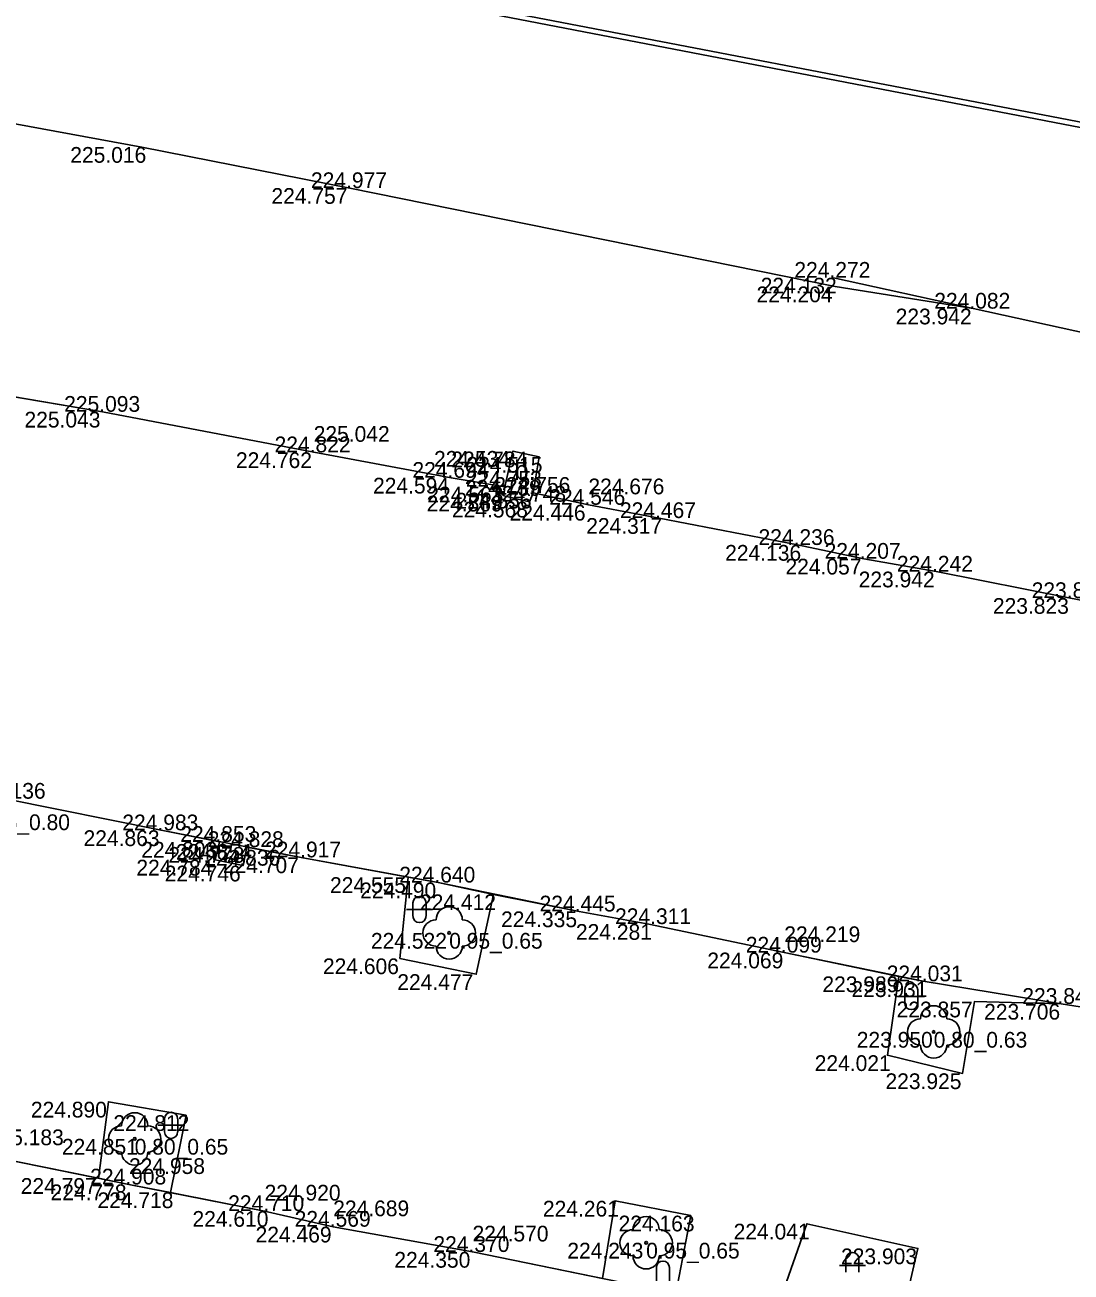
# Model space of a CAD drawing. Extents: x -599516 to -599132, y -1163668 to -1163119.
# Drawn here: x -599349.76 to -599329.8, y -1163179.4 to -1163155.61 of the extents above; entities that cross this region are included whole.
import ezdxf

# ---------------------------------------------------------------- set-up
doc = ezdxf.new("R2010")
doc.units = 0
for name, color, linetype in [('_ZEMERENI OBLAST', 7, 'Continuous'), ('Bod-oznac1', 7, 'Continuous'), ('Bod-oznac2', 7, 'Continuous'), ('Bod-oznac3', 7, 'Continuous'), ('Bod-vyska1', 7, 'Continuous'), ('Bod-vyska2', 7, 'Continuous'), ('Bod-vyska3', 7, 'Continuous'), ('Z_cela-hrobu-dolni-linie', 7, 'Continuous'), ('Z_cela-hrobu-horni-linie', 7, 'Continuous'), ('Z_komunikace', 7, 'Continuous'), ('Z_kultury-znacky', 7, 'Continuous'), ('Z_obvod-kmene-spodek-ve-vysce1_2m', 7, 'Continuous'), ('Z_popis-budov-povrchu', 7, 'Continuous'), ('Z_stromy-kere', 7, 'Continuous'), ('Z_zdi-ohradni', 7, 'Continuous'), ('Z_zpevnene-plochy', 7, 'Continuous')]:
    doc.layers.add(name, color=color, linetype=linetype)

msp = doc.modelspace()

# ---------------------------------------------------------------- linework, layer by layer
at = {"layer": '_ZEMERENI OBLAST'}
msp.add_lwpolyline([(-599246.21, -1163173.61), (-599310.76, -1163161.2), (-599382.471, -1163147.382), (-599418.511, -1163140.298), (-599415.805, -1163126.425), (-599441.73, -1163121.594), (-599445.004, -1163135.25), (-599483.712, -1163127.751), (-599506.25, -1163123.345), (-599510.771, -1163146.476), (-599502.636, -1163301.975), (-599510.038, -1163302.355), (-599510.12, -1163309.17), (-599515.16, -1163309.664), (-599511.204, -1163380.278), (-599506.35, -1163380.56), (-599506.01, -1163391.1), (-599497.946, -1163390.674), (-599491.96, -1163502.01)], dxfattribs=at)
at = {"layer": 'Bod-oznac1'}
for p, q in [((-599347.526, -1163157.941), (-599347.526, -1163157.941)), ((-599343.555, -1163158.724), (-599343.555, -1163158.724)), ((-599334.328, -1163160.434), (-599334.328, -1163160.434)), ((-599334.295, -1163160.601), (-599334.295, -1163160.601)), ((-599331.661, -1163161.023), (-599331.661, -1163161.023)), ((-599348.273, -1163162.99), (-599348.273, -1163162.99)), ((-599344.246, -1163163.763), (-599344.246, -1163163.763)), ((-599340.446, -1163163.738), (-599340.446, -1163163.738)), ((-599339.942, -1163163.851), (-599339.942, -1163163.851)), ((-599341.621, -1163164.249), (-599341.621, -1163164.249)), ((-599340.597, -1163164.419), (-599340.597, -1163164.419)), ((-599340.621, -1163164.591), (-599340.621, -1163164.591)), ((-599340.128, -1163164.705), (-599340.128, -1163164.705)), ((-599340.058, -1163164.536), (-599340.058, -1163164.536)), ((-599339.005, -1163164.764), (-599339.005, -1163164.764)), ((-599337.656, -1163165.017), (-599337.656, -1163165.017)), ((-599335.018, -1163165.53), (-599335.018, -1163165.53)), ((-599333.752, -1163165.793), (-599333.752, -1163165.793)), ((-599332.367, -1163166.038), (-599332.367, -1163166.038)), ((-599329.806, -1163166.543), (-599329.806, -1163166.543)), ((-599347.156, -1163170.972), (-599347.156, -1163170.972)), ((-599346.045, -1163171.192), (-599346.045, -1163171.192)), ((-599345.521, -1163171.291), (-599345.521, -1163171.291)), ((-599346.123, -1163171.534), (-599346.123, -1163171.534)), ((-599345.593, -1163171.646), (-599345.593, -1163171.646)), ((-599344.484, -1163171.488), (-599344.484, -1163171.488)), ((-599342.442, -1163171.866), (-599342.442, -1163171.866)), ((-599341.868, -1163171.968), (-599341.868, -1163171.968)), ((-599340.818, -1163172.194), (-599340.818, -1163172.194)), ((-599339.178, -1163172.519), (-599339.178, -1163172.519)), ((-599337.854, -1163172.76), (-599337.854, -1163172.76)), ((-599341.661, -1163172.929), (-599341.661, -1163172.929)), ((-599335.268, -1163173.304), (-599335.268, -1163173.304)), ((-599342.602, -1163173.415), (-599342.602, -1163173.415)), ((-599341.143, -1163173.716), (-599341.143, -1163173.716)), ((-599333.081, -1163173.758), (-599333.081, -1163173.758)), ((-599332.62, -1163173.851), (-599332.62, -1163173.851)), ((-599331.641, -1163174.239), (-599331.641, -1163174.239)), ((-599329.985, -1163174.282), (-599329.985, -1163174.282)), ((-599332.417, -1163174.817), (-599332.417, -1163174.817)), ((-599333.3, -1163175.262), (-599333.3, -1163175.262)), ((-599331.867, -1163175.607), (-599331.867, -1163175.607)), ((-599348.162, -1163176.149), (-599348.162, -1163176.149)), ((-599346.679, -1163176.405), (-599346.679, -1163176.405)), ((-599347.661, -1163176.857), (-599347.661, -1163176.857)), ((-599348.35, -1163177.605), (-599348.35, -1163177.605)), ((-599347.77, -1163177.726), (-599347.77, -1163177.726)), ((-599346.981, -1163177.877), (-599346.981, -1163177.877)), ((-599338.495, -1163178.038), (-599338.495, -1163178.038)), ((-599345.183, -1163178.233), (-599345.183, -1163178.233)), ((-599337.051, -1163178.321), (-599337.051, -1163178.321)), ((-599343.874, -1163178.532), (-599343.874, -1163178.532)), ((-599334.836, -1163178.475), (-599334.836, -1163178.475)), ((-599341.216, -1163179.013), (-599341.216, -1163179.013)), ((-599337.903, -1163178.838), (-599337.903, -1163178.838)), ((-599332.717, -1163178.947), (-599332.717, -1163178.947))]:
    msp.add_line(p, q, dxfattribs=at)
at = {"layer": 'Bod-oznac2'}
for p, q in [((-599343.555, -1163158.724), (-599343.555, -1163158.724)), ((-599334.328, -1163160.434), (-599334.328, -1163160.434)), ((-599331.661, -1163161.023), (-599331.661, -1163161.023)), ((-599348.273, -1163162.99), (-599348.273, -1163162.99)), ((-599344.246, -1163163.763), (-599344.246, -1163163.763)), ((-599341.621, -1163164.249), (-599341.621, -1163164.249)), ((-599340.597, -1163164.419), (-599340.597, -1163164.419)), ((-599340.621, -1163164.591), (-599340.621, -1163164.591)), ((-599340.128, -1163164.705), (-599340.128, -1163164.705)), ((-599340.058, -1163164.536), (-599340.058, -1163164.536)), ((-599339.005, -1163164.764), (-599339.005, -1163164.764)), ((-599337.656, -1163165.017), (-599337.656, -1163165.017)), ((-599335.018, -1163165.53), (-599335.018, -1163165.53)), ((-599333.752, -1163165.793), (-599333.752, -1163165.793)), ((-599332.367, -1163166.038), (-599332.367, -1163166.038)), ((-599329.806, -1163166.543), (-599329.806, -1163166.543)), ((-599347.156, -1163170.972), (-599347.156, -1163170.972)), ((-599346.045, -1163171.192), (-599346.045, -1163171.192)), ((-599345.521, -1163171.291), (-599345.521, -1163171.291)), ((-599346.123, -1163171.534), (-599346.123, -1163171.534)), ((-599345.593, -1163171.646), (-599345.593, -1163171.646)), ((-599344.484, -1163171.488), (-599344.484, -1163171.488)), ((-599341.868, -1163171.968), (-599341.868, -1163171.968)), ((-599339.178, -1163172.519), (-599339.178, -1163172.519)), ((-599337.854, -1163172.76), (-599337.854, -1163172.76)), ((-599335.268, -1163173.304), (-599335.268, -1163173.304)), ((-599332.62, -1163173.851), (-599332.62, -1163173.851)), ((-599329.985, -1163174.282), (-599329.985, -1163174.282)), ((-599347.77, -1163177.726), (-599347.77, -1163177.726)), ((-599345.183, -1163178.233), (-599345.183, -1163178.233)), ((-599343.874, -1163178.532), (-599343.874, -1163178.532)), ((-599341.216, -1163179.013), (-599341.216, -1163179.013))]:
    msp.add_line(p, q, dxfattribs=at)
at = {"layer": 'Bod-oznac3'}
for p, q in [((-599344.246, -1163163.763), (-599344.246, -1163163.763)), ((-599341.621, -1163164.249), (-599341.621, -1163164.249)), ((-599339.005, -1163164.764), (-599339.005, -1163164.764)), ((-599329.806, -1163166.543), (-599329.806, -1163166.543)), ((-599335.268, -1163173.304), (-599335.268, -1163173.304)), ((-599347.77, -1163177.726), (-599347.77, -1163177.726)), ((-599345.183, -1163178.233), (-599345.183, -1163178.233)), ((-599343.874, -1163178.532), (-599343.874, -1163178.532)), ((-599341.216, -1163179.013), (-599341.216, -1163179.013))]:
    msp.add_line(p, q, dxfattribs=at)
at = {"layer": 'Z_cela-hrobu-dolni-linie'}
msp.add_line((-599331.661, -1163161.023), (-599334.328, -1163160.434), dxfattribs=at)
for points in [[(-599340.597, -1163164.419), (-599340.621, -1163164.591), (-599340.128, -1163164.705), (-599340.058, -1163164.536)], [(-599342.442, -1163171.866), (-599341.868, -1163171.968), (-599340.818, -1163172.194)], [(-599333.081, -1163173.758), (-599332.62, -1163173.851), (-599329.985, -1163174.282)], [(-599346.981, -1163177.877), (-599347.77, -1163177.726), (-599348.35, -1163177.605)]]:
    msp.add_lwpolyline(points, dxfattribs=at)
at = {"layer": 'Z_cela-hrobu-horni-linie'}
for p, q in [((-599343.555, -1163158.724), (-599347.526, -1163157.941)), ((-599334.328, -1163160.434), (-599331.661, -1163161.023)), ((-599348.273, -1163162.99), (-599350.949, -1163162.537)), ((-599337.656, -1163165.017), (-599335.018, -1163165.53)), ((-599347.156, -1163170.972), (-599344.484, -1163171.488)), ((-599344.484, -1163171.488), (-599341.868, -1163171.968)), ((-599341.868, -1163171.968), (-599339.178, -1163172.519)), ((-599339.178, -1163172.519), (-599337.854, -1163172.76)), ((-599332.62, -1163173.851), (-599329.985, -1163174.282))]:
    msp.add_line(p, q, dxfattribs=at)
for points in [[(-599337.656, -1163165.017), (-599339.005, -1163164.764), (-599339.005, -1163164.764), (-599340.058, -1163164.536), (-599340.128, -1163164.705), (-599340.621, -1163164.591), (-599340.597, -1163164.419), (-599341.621, -1163164.249), (-599341.621, -1163164.249), (-599344.246, -1163163.763), (-599344.246, -1163163.763), (-599348.273, -1163162.99)], [(-599332.367, -1163166.038), (-599333.752, -1163165.793)], [(-599321.733, -1163168.099), (-599325.878, -1163167.289), (-599325.878, -1163167.289), (-599329.806, -1163166.543), (-599329.806, -1163166.543), (-599332.367, -1163166.038)], [(-599332.62, -1163173.851), (-599335.268, -1163173.304), (-599335.268, -1163173.304), (-599337.854, -1163172.76)], [(-599355.917, -1163176.145), (-599354.552, -1163176.403), (-599353.148, -1163176.707), (-599350.464, -1163177.177), (-599350.464, -1163177.177), (-599347.77, -1163177.726), (-599347.77, -1163177.726), (-599345.183, -1163178.233), (-599345.183, -1163178.233), (-599343.874, -1163178.532), (-599343.874, -1163178.532), (-599341.216, -1163179.013), (-599341.216, -1163179.013), (-599337.334, -1163179.805)]]:
    msp.add_lwpolyline(points, dxfattribs=at)
at = {"layer": 'Z_komunikace'}
for points in [[(-599318.345, -1163163.663), (-599318.407, -1163163.863), (-599319.412, -1163163.637), (-599319.387, -1163163.49), (-599324.365, -1163162.509), (-599326.887, -1163162.07), (-599331.661, -1163161.023), (-599334.295, -1163160.601), (-599343.555, -1163158.724), (-599347.526, -1163157.941), (-599355.139, -1163156.542), (-599355.776, -1163156.429)], [(-599346.045, -1163171.192), (-599347.156, -1163170.972), (-599350.127, -1163170.369), (-599350.434, -1163171.914), (-599351.934, -1163171.644), (-599352.456, -1163169.969), (-599353.805, -1163169.707), (-599355.141, -1163169.397), (-599357.662, -1163168.965), (-599359.715, -1163168.564), (-599360.045, -1163170.027), (-599361.507, -1163169.757), (-599361.187, -1163168.263), (-599366.903, -1163167.139), (-599367.208, -1163166.321), (-599367.088, -1163165.13), (-599366.227, -1163160.861), (-599365.485, -1163159.922), (-599364.786, -1163159.57)], [(-599350.949, -1163162.537), (-599348.273, -1163162.99), (-599344.246, -1163163.763), (-599341.621, -1163164.249), (-599340.597, -1163164.419), (-599340.446, -1163163.738), (-599339.942, -1163163.851), (-599340.058, -1163164.536), (-599339.005, -1163164.764), (-599337.656, -1163165.017), (-599335.018, -1163165.53), (-599333.752, -1163165.793), (-599332.367, -1163166.038), (-599329.806, -1163166.543), (-599328.119, -1163166.863)], [(-599346.045, -1163171.192), (-599346.123, -1163171.534), (-599345.593, -1163171.646), (-599345.521, -1163171.291)], [(-599325.182, -1163175.133), (-599327.599, -1163174.655), (-599329.985, -1163174.282), (-599331.641, -1163174.239), (-599331.867, -1163175.607), (-599333.3, -1163175.262), (-599333.081, -1163173.758), (-599335.268, -1163173.304), (-599337.854, -1163172.76), (-599339.178, -1163172.519), (-599340.818, -1163172.194), (-599341.143, -1163173.716), (-599342.602, -1163173.415), (-599342.442, -1163171.866), (-599344.484, -1163171.488), (-599345.521, -1163171.291)], [(-599348.35, -1163177.605), (-599348.162, -1163176.149), (-599346.679, -1163176.405), (-599346.981, -1163177.877), (-599345.183, -1163178.233), (-599343.874, -1163178.532), (-599341.216, -1163179.013), (-599338.735, -1163179.518), (-599338.495, -1163178.038), (-599337.051, -1163178.321), (-599337.334, -1163179.805)], [(-599354.922, -1163176.331), (-599354.552, -1163176.403), (-599353.148, -1163176.707), (-599350.464, -1163177.177), (-599348.35, -1163177.605)], [(-599335.358, -1163179.966), (-599334.836, -1163178.475), (-599332.717, -1163178.947), (-599333.072, -1163180.462)]]:
    msp.add_lwpolyline(points, dxfattribs=at)
at = {"layer": 'Z_kultury-znacky'}
for p, q in [((-599342.352, -1163172.356), (-599342.352, -1163172.606)), ((-599342.102, -1163172.356), (-599342.102, -1163172.606)), ((-599342.477, -1163172.481), (-599341.977, -1163172.481)), ((-599332.969, -1163174.017), (-599332.969, -1163174.267)), ((-599332.719, -1163174.017), (-599332.719, -1163174.267)), ((-599333.094, -1163174.142), (-599332.594, -1163174.142)), ((-599347.216, -1163176.598), (-599346.716, -1163176.598)), ((-599347.091, -1163176.473), (-599347.091, -1163176.723)), ((-599346.841, -1163176.473), (-599346.841, -1163176.723)), ((-599334.217, -1163179.271), (-599333.717, -1163179.271)), ((-599334.092, -1163179.146), (-599334.092, -1163179.396)), ((-599333.842, -1163179.146), (-599333.842, -1163179.396)), ((-599337.707, -1163179.312), (-599337.707, -1163179.562)), ((-599337.457, -1163179.312), (-599337.457, -1163179.562))]:
    msp.add_line(p, q, dxfattribs=at)
for centre, start, end in [((-599342.227, -1163172.357), 0, 180), ((-599342.227, -1163172.607), 180, 0), ((-599332.845, -1163174.017), 0, 180), ((-599332.845, -1163174.267), 180, 0), ((-599346.967, -1163176.473), 0, 180), ((-599346.967, -1163176.723), 180, 0), ((-599333.967, -1163179.147), 0, 180), ((-599337.583, -1163179.312), 0, 180)]:
    msp.add_arc(centre, 0.125, start, end, dxfattribs=at)
at = {"layer": 'Z_stromy-kere'}
for centre in [(-599341.661, -1163172.929), (-599332.417, -1163174.817), (-599347.661, -1163176.857), (-599337.903, -1163178.838)]:
    msp.add_circle(centre, 0.025, dxfattribs=at)
for centre, start, end in [((-599341.661, -1163172.679), 0, 180), ((-599341.911, -1163172.929), 90, 270), ((-599341.411, -1163172.929), 270, 90), ((-599341.661, -1163173.179), 180, 0), ((-599332.417, -1163174.567), 0, 180), ((-599332.667, -1163174.817), 90, 270), ((-599332.167, -1163174.817), 270, 90), ((-599332.417, -1163175.067), 180, 0), ((-599347.661, -1163176.607), 0, 180), ((-599347.911, -1163176.857), 90, 270), ((-599347.411, -1163176.857), 270, 90), ((-599347.661, -1163177.107), 180, 0), ((-599337.903, -1163178.588), 0, 180), ((-599338.153, -1163178.838), 90, 270), ((-599337.653, -1163178.838), 270, 90), ((-599337.903, -1163179.088), 180, 0)]:
    msp.add_arc(centre, 0.25, start, end, dxfattribs=at)
at = {"layer": 'Z_zdi-ohradni'}
msp.add_lwpolyline([(-599414.8, -1163140.976), (-599394.798, -1163144.985), (-599376.174, -1163148.484), (-599363.541, -1163150.911), (-599348.224, -1163153.888), (-599326.361, -1163158.089), (-599312.815, -1163160.754)], dxfattribs=at)
at = {"layer": 'Z_zpevnene-plochy'}
msp.add_lwpolyline([(-599346.045, -1163171.192), (-599346.123, -1163171.534), (-599345.593, -1163171.646), (-599345.521, -1163171.291)], dxfattribs=at)

# ---------------------------------------------------------------- texts
at = {"layer": 'Bod-vyska1'}
for s, p in [('225.016', (-599348.89, -1163158.241)), ('224.757', (-599345.052, -1163159.024)), ('224.132', (-599335.717, -1163160.734)), ('224.204', (-599335.797, -1163160.901)), ('223.942', (-599333.142, -1163161.323)), ('225.043', (-599349.764, -1163163.29)), ('224.762', (-599345.729, -1163164.063)), ('224.534', (-599341.95, -1163164.038)), ('224.515', (-599341.331, -1163164.151)), ('224.594', (-599343.114, -1163164.549)), ('224.563', (-599342.078, -1163164.719)), ('224.556', (-599341.54, -1163164.836)), ('224.569', (-599342.091, -1163164.891)), ('224.568', (-599341.609, -1163165.005)), ('224.446', (-599340.509, -1163165.064)), ('224.317', (-599339.047, -1163165.317)), ('224.136', (-599336.396, -1163165.83)), ('224.057', (-599335.245, -1163166.093)), ('223.942', (-599333.848, -1163166.338)), ('223.823', (-599331.288, -1163166.843)), ('224.863', (-599348.637, -1163171.272)), ('224.803', (-599347.536, -1163171.492)), ('224.778', (-599347.018, -1163171.591)), ('224.784', (-599347.629, -1163171.834)), ('224.746', (-599347.088, -1163171.946)), ('224.707', (-599345.979, -1163171.788)), ('224.555', (-599343.935, -1163172.166)), ('224.490', (-599343.359, -1163172.268)), ('224.412', (-599342.218, -1163172.494)), ('224.335', (-599340.671, -1163172.819)), ('224.281', (-599339.243, -1163173.06)), ('224.522', (-599343.154, -1163173.229)), ('224.069', (-599336.736, -1163173.604)), ('224.606', (-599344.07, -1163173.715)), ('224.477', (-599342.651, -1163174.016)), ('223.989', (-599334.54, -1163174.058)), ('223.931', (-599333.986, -1163174.151)), ('223.857', (-599333.124, -1163174.539)), ('223.706', (-599331.455, -1163174.582)), ('223.950', (-599333.885, -1163175.117)), ('224.021', (-599334.687, -1163175.562)), ('223.925', (-599333.337, -1163175.907)), ('224.890', (-599349.642, -1163176.449)), ('224.812', (-599348.068, -1163176.705)), ('224.851', (-599349.05, -1163177.157)), ('224.797', (-599349.835, -1163177.905)), ('224.778', (-599349.267, -1163178.026)), ('224.718', (-599348.372, -1163178.177)), ('224.261', (-599339.873, -1163178.338)), ('224.610', (-599346.559, -1163178.533)), ('224.163', (-599338.429, -1163178.621)), ('224.469', (-599345.355, -1163178.832)), ('224.041', (-599336.234, -1163178.775)), ('224.350', (-599342.707, -1163179.313)), ('224.243', (-599339.407, -1163179.138)), ('223.903', (-599334.185, -1163179.247))]:
    msp.add_text(s, height=0.3, dxfattribs=at).set_placement(p)
at = {"layer": 'Bod-vyska2'}
for s, p in [('224.977', (-599344.298, -1163158.724)), ('224.272', (-599335.075, -1163160.434)), ('224.082', (-599332.406, -1163161.023)), ('225.093', (-599349.007, -1163162.99)), ('224.822', (-599344.992, -1163163.763)), ('224.694', (-599342.362, -1163164.249)), ('224.739', (-599341.363, -1163164.591)), ('224.753', (-599341.344, -1163164.419)), ('224.756', (-599340.8, -1163164.536)), ('224.748', (-599340.881, -1163164.705)), ('224.546', (-599339.751, -1163164.764)), ('224.467', (-599338.403, -1163165.017)), ('224.236', (-599335.759, -1163165.53)), ('224.207', (-599334.498, -1163165.793)), ('224.242', (-599333.119, -1163166.038)), ('223.853', (-599330.547, -1163166.543)), ('225.136', (-599350.81, -1163170.369)), ('224.983', (-599347.897, -1163170.972)), ('224.853', (-599346.791, -1163171.192)), ('224.828', (-599346.267, -1163171.291)), ('224.917', (-599345.174, -1163171.488)), ('224.854', (-599346.875, -1163171.534)), ('224.836', (-599346.334, -1163171.646)), ('224.640', (-599342.613, -1163171.968)), ('224.445', (-599339.936, -1163172.519)), ('224.311', (-599338.496, -1163172.76)), ('224.099', (-599336.002, -1163173.304)), ('224.031', (-599333.313, -1163173.851)), ('223.846', (-599330.726, -1163174.282)), ('224.908', (-599348.51, -1163177.726)), ('224.710', (-599345.877, -1163178.233)), ('224.569', (-599344.609, -1163178.532)), ('224.370', (-599341.962, -1163179.013))]:
    msp.add_text(s, height=0.3, dxfattribs=at).set_placement(p)
at = {"layer": 'Bod-vyska3'}
for s, p in [('225.042', (-599344.246, -1163163.563)), ('224.784', (-599341.621, -1163164.049)), ('224.676', (-599339.005, -1163164.564)), ('224.219', (-599335.268, -1163173.104)), ('225.183', (-599350.464, -1163176.977)), ('224.958', (-599347.77, -1163177.526)), ('224.920', (-599345.183, -1163178.033)), ('224.689', (-599343.874, -1163178.332)), ('224.570', (-599341.216, -1163178.813))]:
    msp.add_text(s, height=0.3, dxfattribs=at).set_placement(p)
at = {"layer": 'Z_obvod-kmene-spodek-ve-vysce1_2m'}
for s, p in [('0.95_0.80', (-599350.681, -1163170.968)), ('0.95_0.65', (-599341.661, -1163173.229)), ('0.80_0.63', (-599332.417, -1163175.117)), ('0.80_0.65', (-599347.661, -1163177.157)), ('0.95_0.65', (-599337.903, -1163179.138))]:
    msp.add_text(s, height=0.3, dxfattribs=at).set_placement(p)
at = {"layer": 'Z_popis-budov-povrchu'}
msp.add_text('b.', height=0.375, dxfattribs=at).set_placement((-599340.422, -1163164.293))

doc.saveas('drawing.dxf')
